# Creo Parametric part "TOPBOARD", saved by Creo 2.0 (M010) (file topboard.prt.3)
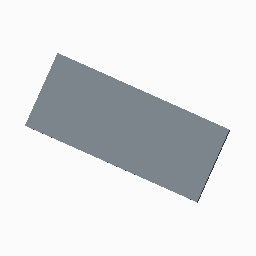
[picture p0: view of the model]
Units: Inch lbm Second (Pro/E Default); INCH, POUND, SECS

Created from: INLBS_PART_SOLID.PRT

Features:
  1. datum plane "RIGHT"
  2. datum plane "TOP"
  3. datum plane "FRONT"
  4. coordinate system
  5. sketch "Sketch 1"
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
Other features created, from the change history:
  extrusion "Extrude 1"

Surfaces: 9 plane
